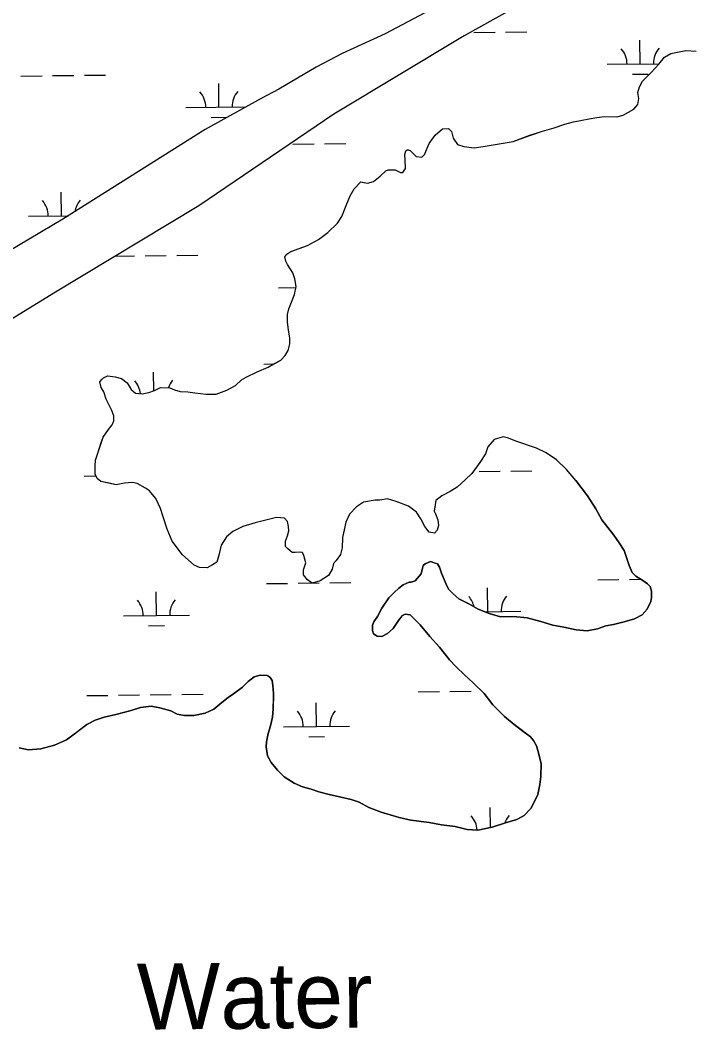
# Model space of a CAD drawing. Extents: x 3684037 to 3722149, y 433263 to 459021.
# Drawn here: x 3699257 to 3700273, y 445838 to 447368 of the extents above; entities that cross this region are included whole.
import ezdxf

# ---------------------------------------------------------------- set-up
doc = ezdxf.new("R2010")
doc.units = 0
for name, color, linetype in [('V-RIVR-IDEN', 7, 'Continuous'), ('V-TOPO-SHOR', 7, 'Continuous'), ('V-WETL-SWMP', 7, 'Continuous')]:
    doc.layers.add(name, color=color, linetype=linetype)

msp = doc.modelspace()

# ---------------------------------------------------------------- linework, layer by layer
at = {"layer": 'V-TOPO-SHOR'}
for points in [[(3700267.9, 447619.3), (3700149.1, 447547.3), (3700000.6, 447453.1), (3699896.1, 447392.7), (3699810.2, 447347), (3699745.2, 447317.1), (3699705.4, 447296.6), (3699649.3, 447263.3), (3699622.2, 447248.9), (3699537.8, 447202), (3699322, 447066.1), (3699069, 446916.1), (3698821, 446758.1), (3698631.4, 446638.4), (3698564.5, 446599.2), (3698525, 446580.2), (3698518.8, 446576.5)], [(3700051.7, 447412.8), (3699929.5, 447343.9), (3699732.6, 447225.3), (3699527.9, 447086.6), (3699308.6, 446954.1), (3699125.2, 446841.4)], [(3700119.2, 447218.5), (3700130.4, 447220.5), (3700142.4, 447221.7), (3700160.7, 447221.3), (3700170.3, 447223.7), (3700186.7, 447232.9), (3700192.6, 447240.1), (3700194.2, 447249.2), (3700192.6, 447258.4), (3700195, 447266.8), (3700199.8, 447275.2), (3700213.4, 447288.8), (3700224.5, 447301.1), (3700232.9, 447311.5), (3700242.9, 447317.1), (3700265.6, 447321.9), (3700280.8, 447320.7)], [(3699399.5, 446760.6), (3699399.1, 446768.2), (3699395.9, 446777.3), (3699387.9, 446793.7), (3699384.3, 446804.5), (3699379.9, 446811.3), (3699377.9, 446820), (3699381.5, 446824), (3699383.5, 446826), (3699389.5, 446828.8), (3699401.4, 446827.2), (3699411, 446824.9), (3699419.4, 446818.5), (3699425.4, 446808.1), (3699432.2, 446802.5), (3699442.2, 446801.7), (3699452.5, 446803.7), (3699460.9, 446806.9), (3699469.7, 446811.3), (3699484.1, 446810.9), (3699490.9, 446807.7), (3699499.6, 446805), (3699511.2, 446804.6), (3699522, 446803), (3699539.1, 446801), (3699554.3, 446801), (3699570.3, 446807), (3699583.4, 446814.2), (3699592.6, 446822.6), (3699599.4, 446827), (3699616.2, 446835), (3699632.9, 446842.2), (3699641.7, 446847), (3699652.1, 446852.5), (3699658.9, 446859.7), (3699663.2, 446867.3), (3699665.6, 446877.3), (3699666, 446886.5), (3699664, 446898.1), (3699662, 446910.8), (3699662.4, 446921.6), (3699664.4, 446930.4), (3699668.4, 446940.4), (3699672.8, 446951.9), (3699675.5, 446964.3), (3699673.5, 446975.9), (3699670.3, 446985.1), (3699662.4, 446997.8), (3699659.6, 447002.6), (3699658.4, 447009.4), (3699661.1, 447013), (3699667.5, 447017.4), (3699678.3, 447021.4), (3699692.3, 447026.6), (3699709, 447035.4), (3699723.4, 447046.2), (3699737.8, 447060.2), (3699744.5, 447070.1), (3699750.9, 447086.9), (3699756.9, 447101.7), (3699763.3, 447112.1), (3699773.2, 447122.8), (3699775.2, 447122.4), (3699783.2, 447120.8), (3699792.4, 447123.2), (3699802.4, 447131.6), (3699811.1, 447139.6), (3699814.7, 447141.2), (3699825.1, 447141.2), (3699833.5, 447137.2), (3699837.1, 447136.9), (3699840.7, 447143.2), (3699840.3, 447155.6), (3699839.9, 447164.4), (3699841.5, 447169.6), (3699843.5, 447171.2), (3699845.4, 447171.2), (3699848.2, 447170.4), (3699852.2, 447166.4), (3699857, 447161.2), (3699865.4, 447160), (3699870.2, 447164.8), (3699872.2, 447170.4), (3699876.6, 447180.8), (3699885.7, 447193.6), (3699896.9, 447203.1), (3699906.1, 447203.5), (3699910.5, 447199.2), (3699912.9, 447188.8), (3699919.7, 447179.6), (3699929.3, 447176.4), (3699944.8, 447174.4), (3699958.4, 447176.4), (3700003.9, 447184.1), (3700029.4, 447193.3), (3700048.2, 447199.6), (3700066.1, 447204.8), (3700082.1, 447210), (3700095.3, 447213.6), (3700108.4, 447216.1), (3700119.2, 447218.5)], [(3700098.8, 446670.4), (3700084.8, 446686.8), (3700069.7, 446701.5), (3700054.1, 446712.3), (3700039.3, 446719.5), (3700008.2, 446729.8), (3699997, 446734.6), (3699989, 446736.6), (3699975.4, 446732.6), (3699965.5, 446721.4), (3699961.9, 446710.7), (3699953.5, 446697.5), (3699941.2, 446680.7), (3699931.2, 446671.1), (3699919.2, 446660.3), (3699908.4, 446653.5), (3699895.7, 446647.2), (3699886.9, 446640), (3699884.5, 446624), (3699886.1, 446620), (3699890.1, 446610.8), (3699890.9, 446602), (3699888.9, 446594.9), (3699884.9, 446590.5), (3699876.6, 446592.1), (3699870.2, 446600.8), (3699864.2, 446612.4), (3699857.4, 446622.4), (3699845.4, 446631.6), (3699827, 446638.7), (3699813.5, 446642.3), (3699801.9, 446640.3), (3699795.1, 446640.7), (3699777.1, 446637.5), (3699766.8, 446630.3), (3699756, 446619.5), (3699750.8, 446607.1), (3699748, 446594.8), (3699745.6, 446584), (3699744.9, 446568.4), (3699742.5, 446558), (3699735.7, 446548.9), (3699732.1, 446544.5), (3699730.1, 446536.1), (3699724.5, 446526.1), (3699711.8, 446518.5), (3699699.4, 446514.9), (3699692.6, 446519.7), (3699686.6, 446527.3), (3699686.6, 446534.9), (3699689.8, 446545.6), (3699687, 446556.4), (3699685, 446561.2), (3699680.6, 446561.6), (3699673.8, 446561.2), (3699669.4, 446561.2), (3699662.6, 446566.8), (3699659, 446570.4), (3699659.4, 446578.4), (3699662.2, 446586.3), (3699664.2, 446593.9), (3699663.8, 446600.7), (3699662.2, 446608.3), (3699657.8, 446613.1), (3699645.4, 446614.3), (3699613.1, 446606.3), (3699594.4, 446600.7), (3699579.6, 446593.1), (3699570, 446584.7), (3699562, 446572.3), (3699560.5, 446565.9), (3699558.5, 446557.1), (3699555.3, 446546.4), (3699548.9, 446542.4), (3699540.5, 446538), (3699528.9, 446538.4), (3699521, 446541.9), (3699503, 446557.5), (3699487.4, 446578.6), (3699480.2, 446596.6), (3699473.8, 446615.3), (3699469.8, 446627.7), (3699463, 446642.9), (3699453.4, 446654.5), (3699447, 446658.8), (3699434.7, 446665.6), (3699427.5, 446667.2), (3699415.5, 446666), (3699402.7, 446663.6), (3699392, 446666), (3699379.6, 446668.8), (3699374, 446673.2), (3699370.8, 446679.9), (3699370.8, 446692.7), (3699371.6, 446701.1), (3699375.6, 446713.1), (3699380.3, 446727.8), (3699383.1, 446736.2), (3699391.1, 446747.8), (3699396.7, 446754.6), (3699399.5, 446760.6)], [(3700098.8, 446670.4), (3700116.3, 446647.1), (3700129.1, 446627.4), (3700138.4, 446610.7), (3700147.1, 446599.3), (3700156.5, 446587.4), (3700164.6, 446576), (3700172.2, 446564.1), (3700176.2, 446552.2), (3700179.6, 446541.5), (3700184.2, 446530.7), (3700189.5, 446525.3), (3700200.1, 446518.7), (3700207.2, 446513.9), (3700211.3, 446509.7), (3700213.5, 446502.5), (3700213.4, 446493), (3700212.2, 446487.1), (3700206.7, 446475.4), (3700199.5, 446466.5), (3700187.6, 446460.8), (3700172.1, 446456.2), (3700156, 446452.3), (3700144.2, 446450), (3700131.7, 446445.4), (3700116.2, 446442.7), (3700099.1, 446444.1), (3700080.7, 446447.8), (3700064.2, 446451), (3700045.9, 446456.5), (3700025.2, 446462.1), (3700004.5, 446464.2), (3699984.9, 446463.8), (3699967.8, 446468.7), (3699950.7, 446475.5), (3699936.6, 446483.3), (3699921.8, 446491.2), (3699913, 446498.4), (3699906, 446505.6), (3699902, 446514), (3699899.7, 446520.5), (3699895.6, 446530.1), (3699892.2, 446539), (3699889.3, 446543.8), (3699885.7, 446545), (3699878.7, 446547.5), (3699870.9, 446544), (3699867.9, 446541.7), (3699866.7, 446537.5), (3699864.8, 446528.7), (3699855.8, 446518.1), (3699849.3, 446516.4), (3699846.3, 446516.4), (3699837.4, 446512.4), (3699830.8, 446507.1), (3699823.6, 446500.7), (3699815.8, 446492.5), (3699804.9, 446476.6), (3699798.3, 446464.3), (3699792.8, 446456), (3699791, 446451.3), (3699790.9, 446443), (3699792.6, 446437.7), (3699797.9, 446434.6), (3699805, 446434), (3699813.9, 446438.6), (3699822.3, 446446.2), (3699831.4, 446459.7), (3699835, 446463.8), (3699835.6, 446465), (3699840.4, 446467.9), (3699848.1, 446466.6), (3699863.3, 446451.6), (3699877.9, 446433.7), (3699892.5, 446417.5), (3699907.7, 446398.4), (3699917.6, 446388.2), (3699930.5, 446375.6), (3699943.4, 446363.6), (3699959.8, 446347.4), (3699973.2, 446330.6), (3699990.8, 446312.6), (3700005.5, 446300.6), (3700016.6, 446292.2), (3700030.1, 446281.9), (3700034.8, 446276.5), (3700039.5, 446268.2), (3700042.3, 446257.5), (3700046.2, 446240.8), (3700046, 446221.9), (3700044.1, 446209.5), (3700041.5, 446194.7), (3700036.7, 446184.7), (3700030.6, 446173.5), (3700020.4, 446162.9), (3700009.7, 446156.5), (3699992.4, 446151.4), (3699972.2, 446145.1), (3699950.2, 446140.7), (3699934.2, 446141.4)], [(3699934.2, 446141.4), (3699915.9, 446145.8), (3699895.2, 446148.4), (3699876.9, 446152.2), (3699849.1, 446155.5), (3699831.3, 446159.9), (3699804.2, 446167.9), (3699785.3, 446174.6), (3699770.6, 446183.1), (3699758.8, 446186.8), (3699741, 446191.2), (3699725.1, 446194.3), (3699709.7, 446198.7), (3699697.9, 446202.4), (3699684.9, 446206.1), (3699672.5, 446211.6), (3699657.2, 446221.2), (3699647.3, 446231.4), (3699637.4, 446242.8), (3699632.2, 446252.9), (3699629.9, 446266.6), (3699630.6, 446274.3), (3699633.1, 446286.7), (3699636.3, 446298.5), (3699639.4, 446311.5), (3699640.7, 446324.5), (3699640.9, 446339.9), (3699641, 446347.6), (3699640, 446359.5), (3699638.9, 446367.2), (3699636, 446372), (3699633.6, 446373.8), (3699631.3, 446375), (3699620.6, 446375.1), (3699611.7, 446372.9), (3699602.7, 446365.9), (3699594.3, 446357.1), (3699580.5, 446347.2), (3699572.2, 446341.4), (3699562.6, 446333.8), (3699550.6, 446323.8), (3699537.5, 446317.5), (3699520.3, 446314.1), (3699506.1, 446314.3), (3699495.4, 446316.2), (3699485.4, 446321.1), (3699468.9, 446326), (3699455.9, 446328.5), (3699439.8, 446326.4), (3699425.6, 446321.8), (3699402.4, 446315.6), (3699384.6, 446311.6), (3699370.9, 446307), (3699358.3, 446300.7), (3699344.6, 446290.2), (3699327.8, 446277.3), (3699309.4, 446269.3), (3699288.6, 446263.6), (3699270.2, 446262), (3699256, 446265.2)]]:
    msp.add_lwpolyline(points, dxfattribs=at)
at = {"layer": 'V-WETL-SWMP'}
for p, q in [((3699944.5, 447349.3), (3699976.5, 447349.6)), ((3699992.5, 447349.8), (3700024.5, 447350.2)), ((3700196.4, 447301.4), (3700196, 447337.4)), ((3700146.4, 447300.9), (3700225.1, 447301.8)), ((3699258.6, 447283.2), (3699290.6, 447283.6)), ((3699306.6, 447283.8), (3699338.6, 447284.1)), ((3699354.6, 447284.3), (3699386.6, 447284.7)), ((3699558.5, 447235.9), (3699558.1, 447271.9)), ((3700184.6, 447285.9), (3700208.6, 447286.2)), ((3699508.5, 447235.4), (3699599.7, 447236.4)), ((3699546.7, 447220.4), (3699570.7, 447220.7)), ((3699670.5, 447179.9), (3699702.5, 447180.3)), ((3699718.5, 447180.4), (3699750.5, 447180.8)), ((3699319.9, 447071.3), (3699319.5, 447107.3)), ((3699269.9, 447070.7), (3699330.5, 447071.4)), ((3699446.5, 447010.8), (3699478.5, 447011.1)), ((3699494.5, 447011.3), (3699526.5, 447011.7)), ((3699401.5, 447010.2), (3699430.5, 447010.6)), ((3699648.4, 446962.4), (3699675.2, 446962.7)), ((3699626.4, 446846.7), (3699641.6, 446846.9)), ((3699459.8, 446806.5), (3699459.4, 446834.3)), ((3699354.4, 446677), (3699372.1, 446677.2)), ((3699952.3, 446684), (3699984.3, 446684.3)), ((3700000.3, 446684.5), (3700032.3, 446684.9)), ((3699630.2, 446514), (3699662.2, 446514.4)), ((3699678.2, 446514.6), (3699710.2, 446515)), ((3699726.2, 446515.1), (3699758.2, 446515.5)), ((3699965.6, 446471.5), (3699965.2, 446507.5)), ((3700132.1, 446519.9), (3700164.1, 446520.2)), ((3700180.1, 446520.4), (3700197, 446520.6)), ((3699463.7, 446465.7), (3699463.3, 446501.7)), ((3699413.7, 446465.1), (3699513.7, 446466.2)), ((3699960.9, 446471.4), (3700015.6, 446472.1)), ((3699451.9, 446450.1), (3699475.9, 446450.4)), ((3699358.3, 446344.3), (3699390.3, 446344.7)), ((3699406.3, 446344.9), (3699438.3, 446345.3)), ((3699454.3, 446345.5), (3699486.3, 446345.8)), ((3699502.3, 446346), (3699534.3, 446346.4)), ((3699860.2, 446350.2), (3699892.2, 446350.6)), ((3699908.2, 446350.7), (3699940.2, 446351.1)), ((3699706.2, 446297.7), (3699705.8, 446333.6)), ((3699656.2, 446297.1), (3699756.2, 446298.2)), ((3699694.4, 446282.1), (3699718.4, 446282.4)), ((3699969.4, 446144.6), (3699969.1, 446174.8))]:
    msp.add_line(p, q, dxfattribs=at)
for points in [[(3700051.7, 447412.8), (3699929.5, 447343.9), (3699732.6, 447225.3), (3699527.9, 447086.6), (3699308.6, 446954.1), (3699125.2, 446841.4)], [(3699896.1, 447392.7), (3699810.2, 447347), (3699745.2, 447317.1), (3699705.4, 447296.6), (3699649.3, 447263.3), (3699622.2, 447248.9), (3699537.8, 447202), (3699322, 447066.1), (3699069, 446916.1)], [(3700186.7, 447232.9), (3700192.6, 447240.1), (3700194.2, 447249.2), (3700192.6, 447258.4), (3700195, 447266.8), (3700199.8, 447275.2), (3700213.4, 447288.8), (3700224.5, 447301.1), (3700232.9, 447311.5), (3700242.9, 447317.1), (3700265.6, 447321.9), (3700280.8, 447320.7)], [(3699256, 446265.2), (3699270.2, 446262), (3699288.6, 446263.6), (3699309.4, 446269.3), (3699327.8, 446277.3), (3699358.3, 446300.7), (3699370.9, 446307), (3699384.6, 446311.6), (3699402.4, 446315.6), (3699425.6, 446321.8), (3699439.8, 446326.4), (3699455.9, 446328.5), (3699468.9, 446326), (3699485.4, 446321.1), (3699495.4, 446316.2), (3699506.1, 446314.3), (3699520.3, 446314.1), (3699537.5, 446317.5), (3699550.6, 446323.8), (3699562.6, 446333.8), (3699572.2, 446341.4), (3699580.5, 446347.2), (3699594.3, 446357.1), (3699602.7, 446365.9), (3699611.7, 446372.9), (3699620.6, 446375.1), (3699631.2, 446375), (3699633.6, 446373.8), (3699636, 446372), (3699638.9, 446367.2), (3699640, 446359.5), (3699641, 446347.6), (3699640.7, 446324.5), (3699639.4, 446311.5), (3699636.3, 446298.5), (3699633.2, 446286.7), (3699630.6, 446274.3), (3699629.9, 446266.6), (3699632.2, 446252.9), (3699637.4, 446242.8), (3699647.3, 446231.4), (3699657.3, 446221.2), (3699672.5, 446211.6), (3699684.9, 446206.1), (3699697.9, 446202.4), (3699709.7, 446198.7), (3699725.1, 446194.3), (3699741, 446191.2), (3699758.8, 446186.8), (3699770.6, 446183.1), (3699785.3, 446174.6), (3699804.2, 446167.9), (3699831.3, 446159.9), (3699849.1, 446155.5), (3699876.9, 446152.2), (3699895.2, 446148.4), (3699915.9, 446145.8), (3699934.2, 446141.4), (3699950.2, 446140.7), (3699972.2, 446145.1), (3699992.4, 446151.4), (3700009.7, 446156.5), (3700020.4, 446162.9), (3700030.6, 446173.5), (3700036.7, 446184.7), (3700041.5, 446194.7), (3700044.1, 446209.5), (3700046, 446221.9), (3700046.2, 446240.8), (3700042.3, 446257.5), (3700039.5, 446268.2), (3700034.8, 446276.5), (3700030.1, 446281.9), (3700005.5, 446300.6), (3699990.8, 446312.6), (3699973.2, 446330.6), (3699959.8, 446347.4), (3699943.4, 446363.6), (3699930.5, 446375.6), (3699917.6, 446388.2), (3699907.7, 446398.4), (3699892.5, 446417.5), (3699877.9, 446433.7), (3699863.3, 446451.6), (3699848.1, 446466.6), (3699840.4, 446467.9), (3699835.6, 446465), (3699835, 446463.8), (3699831.4, 446459.7), (3699822.3, 446446.2), (3699813.9, 446438.6), (3699805, 446434), (3699797.9, 446434.6), (3699792.6, 446437.7), (3699790.9, 446443), (3699791, 446451.3), (3699792.8, 446456), (3699798.3, 446464.3), (3699804.9, 446476.6), (3699815.8, 446492.5), (3699823.6, 446500.7), (3699830.8, 446507.1), (3699837.4, 446512.4), (3699846.3, 446516.4), (3699849.3, 446516.4), (3699855.8, 446518.1), (3699864.8, 446528.7), (3699866.7, 446537.5), (3699867.9, 446541.7), (3699870.9, 446544), (3699878.7, 446547.4), (3699889.3, 446543.8), (3699892.2, 446539), (3699895.6, 446530.1), (3699899.7, 446520.5), (3699902, 446514), (3699906, 446505.6), (3699913, 446498.4), (3699921.8, 446491.2), (3699936.6, 446483.3), (3699950.7, 446475.5), (3699967.8, 446468.7), (3699984.9, 446463.8), (3700004.5, 446464.2), (3700025.2, 446462.1), (3700045.9, 446456.5), (3700064.2, 446451), (3700080.7, 446447.8), (3700099.1, 446444.1), (3700116.2, 446442.7), (3700131.7, 446445.4), (3700144.2, 446450), (3700156, 446452.3), (3700172.1, 446456.2), (3700187.6, 446460.8), (3700199.5, 446466.5), (3700206.7, 446475.3), (3700212.2, 446487.1), (3700213.4, 446493), (3700213.5, 446502.5), (3700211.3, 446509.7), (3700207.2, 446513.9), (3700200.1, 446518.7), (3700189.5, 446525.3), (3700184.2, 446530.7), (3700179.6, 446541.5), (3700176.2, 446552.2), (3700172.2, 446564.1), (3700164.6, 446576), (3700156.5, 446587.4), (3700138.4, 446610.7), (3700129.1, 446627.4), (3700116.3, 446647.1), (3700098.8, 446670.4), (3700084.8, 446686.8), (3700069.7, 446701.5), (3700054.1, 446712.3), (3700039.3, 446719.5), (3700008.2, 446729.8), (3699997, 446734.6), (3699989, 446736.6), (3699975.4, 446732.6), (3699965.5, 446721.4), (3699961.9, 446710.7), (3699953.5, 446697.5), (3699941.2, 446680.7), (3699931.2, 446671.1), (3699919.2, 446660.3), (3699908.4, 446653.5), (3699895.7, 446647.2), (3699886.9, 446640), (3699884.5, 446624), (3699886.1, 446620), (3699890.1, 446610.8), (3699890.9, 446602), (3699888.9, 446594.9), (3699884.9, 446590.5), (3699876.6, 446592.1), (3699870.2, 446600.8), (3699864.2, 446612.4), (3699857.4, 446622.4), (3699845.4, 446631.6), (3699827, 446638.7), (3699813.5, 446642.3), (3699801.9, 446640.3), (3699795.1, 446640.7), (3699777.1, 446637.5), (3699766.8, 446630.3), (3699756, 446619.5), (3699750.8, 446607.1), (3699745.6, 446584), (3699744.9, 446568.4), (3699742.5, 446558), (3699735.7, 446548.9), (3699732.1, 446544.5), (3699730.1, 446536.1), (3699724.5, 446526.1), (3699711.8, 446518.5), (3699699.4, 446514.9), (3699692.6, 446519.7), (3699686.6, 446527.3), (3699686.6, 446534.9), (3699689.8, 446545.6), (3699687, 446556.4), (3699685, 446561.2), (3699680.6, 446561.6), (3699673.8, 446561.2), (3699669.4, 446561.2), (3699662.6, 446566.8), (3699659, 446570.4), (3699659.4, 446578.4), (3699662.2, 446586.3), (3699664.2, 446593.9), (3699663.8, 446600.7), (3699662.2, 446608.3), (3699657.8, 446613.1), (3699645.4, 446614.3), (3699613.1, 446606.3), (3699594.4, 446600.7), (3699579.6, 446593.1), (3699570, 446584.7), (3699562, 446572.3), (3699560.5, 446565.9), (3699558.5, 446557.1), (3699555.3, 446546.4), (3699548.9, 446542.4), (3699540.5, 446538), (3699528.9, 446538.4), (3699521, 446541.9), (3699503, 446557.5), (3699487.4, 446578.6), (3699480.2, 446596.6), (3699473.8, 446615.3), (3699469.8, 446627.7), (3699463, 446642.9), (3699453.4, 446654.5), (3699447, 446658.8), (3699434.7, 446665.6), (3699427.5, 446667.2), (3699415.5, 446666), (3699402.7, 446663.6), (3699379.6, 446668.8), (3699374, 446673.2), (3699370.8, 446679.9), (3699370.8, 446692.7), (3699371.6, 446701.1), (3699383.1, 446736.2), (3699391.1, 446747.8), (3699396.7, 446754.6), (3699399.5, 446760.6), (3699399.1, 446768.2), (3699395.9, 446777.3), (3699387.9, 446793.7), (3699384.3, 446804.5), (3699379.9, 446811.3), (3699377.9, 446820), (3699381.5, 446824), (3699383.5, 446826), (3699389.5, 446828.8), (3699401.4, 446827.2), (3699411, 446824.9), (3699419.4, 446818.5), (3699425.4, 446808.1), (3699432.2, 446802.5), (3699442.2, 446801.7), (3699452.5, 446803.7), (3699460.9, 446806.9), (3699469.7, 446811.3), (3699484.1, 446810.9), (3699490.9, 446807.7), (3699499.6, 446805), (3699511.2, 446804.6), (3699522, 446803), (3699539.1, 446801), (3699554.3, 446801), (3699570.3, 446807), (3699583.4, 446814.2), (3699592.6, 446822.6), (3699599.4, 446827), (3699616.2, 446835), (3699632.9, 446842.2), (3699652.1, 446852.5), (3699658.9, 446859.7), (3699663.2, 446867.3), (3699665.6, 446877.3), (3699666, 446886.5), (3699664, 446898.1), (3699662, 446910.8), (3699662.4, 446921.6), (3699664.4, 446930.4), (3699668.4, 446940.4), (3699672.8, 446951.9), (3699675.5, 446964.3), (3699673.5, 446975.9), (3699670.3, 446985.1), (3699662.4, 446997.8), (3699659.6, 447002.6), (3699658.4, 447009.4), (3699661.1, 447013), (3699667.5, 447017.4), (3699692.3, 447026.6), (3699709, 447035.4), (3699723.4, 447046.2), (3699737.8, 447060.2), (3699744.5, 447070.1), (3699750.9, 447086.9), (3699756.9, 447101.7), (3699763.3, 447112.1), (3699773.2, 447122.8), (3699783.2, 447120.8), (3699792.4, 447123.2), (3699802.4, 447131.6), (3699811.1, 447139.6), (3699814.7, 447141.2), (3699825.1, 447141.2), (3699833.5, 447137.2), (3699837.1, 447136.8), (3699840.7, 447143.2), (3699840.3, 447155.6), (3699839.9, 447164.4), (3699841.5, 447169.6), (3699843.5, 447171.2), (3699845.4, 447171.2), (3699848.2, 447170.4), (3699852.2, 447166.4), (3699857, 447161.2), (3699865.4, 447160), (3699870.2, 447164.8), (3699872.2, 447170.4), (3699876.6, 447180.8), (3699885.7, 447193.6), (3699896.9, 447203.1), (3699906.1, 447203.5), (3699910.5, 447199.2), (3699912.9, 447188.8), (3699919.7, 447179.6), (3699929.3, 447176.4), (3699944.8, 447174.4), (3699958.4, 447176.4), (3700003.9, 447184.1), (3700029.4, 447193.2), (3700048.2, 447199.6), (3700066.1, 447204.8), (3700082.1, 447210), (3700095.3, 447213.6), (3700108.4, 447216.1), (3700119.2, 447218.5), (3700130.4, 447220.5), (3700142.4, 447221.7), (3700160.7, 447221.3), (3700170.3, 447223.7), (3700186.7, 447232.9)]]:
    msp.add_lwpolyline(points, dxfattribs=at)
for centre, start, end in [((3700141.2, 447301.3), 359.8949, 41.4385), ((3700251.7, 447302.6), 139.8949, 181.4385), ((3699503.3, 447235.8), 359.8949, 41.4385), ((3699613.7, 447237.1), 139.8949, 181.4385), ((3699264.7, 447071.1), 359.8949, 41.4385), ((3699375.2, 447072.4), 139.8949, 171.528), ((3699643.2, 446962.8), 40.7304, 41.4385), ((3699404.6, 446798.1), 6.163, 41.4385), ((3699515.1, 446799.4), 139.8949, 160.8394), ((3699910.4, 446471.3), 12.1416, 41.4385), ((3700020.8, 446472.6), 139.8949, 181.4385), ((3699408.5, 446465.5), 359.8949, 41.4385), ((3699519, 446466.8), 139.8949, 181.4385), ((3699650.9, 446297.5), 359.8949, 41.4385), ((3699761.4, 446298.8), 139.8949, 181.4385), ((3699914.2, 446138.7), 3.2828, 41.4385), ((3700024.7, 446140), 139.8949, 161.6702)]:
    msp.add_arc(centre, 35.2, start, end, dxfattribs=at)

# ---------------------------------------------------------------- texts
at = {"layer": 'V-RIVR-IDEN'}
msp.add_text('Water', height=100, rotation=0.5305, dxfattribs=at).set_placement((3699434.7, 445838.1))

doc.saveas('drawing.dxf')
